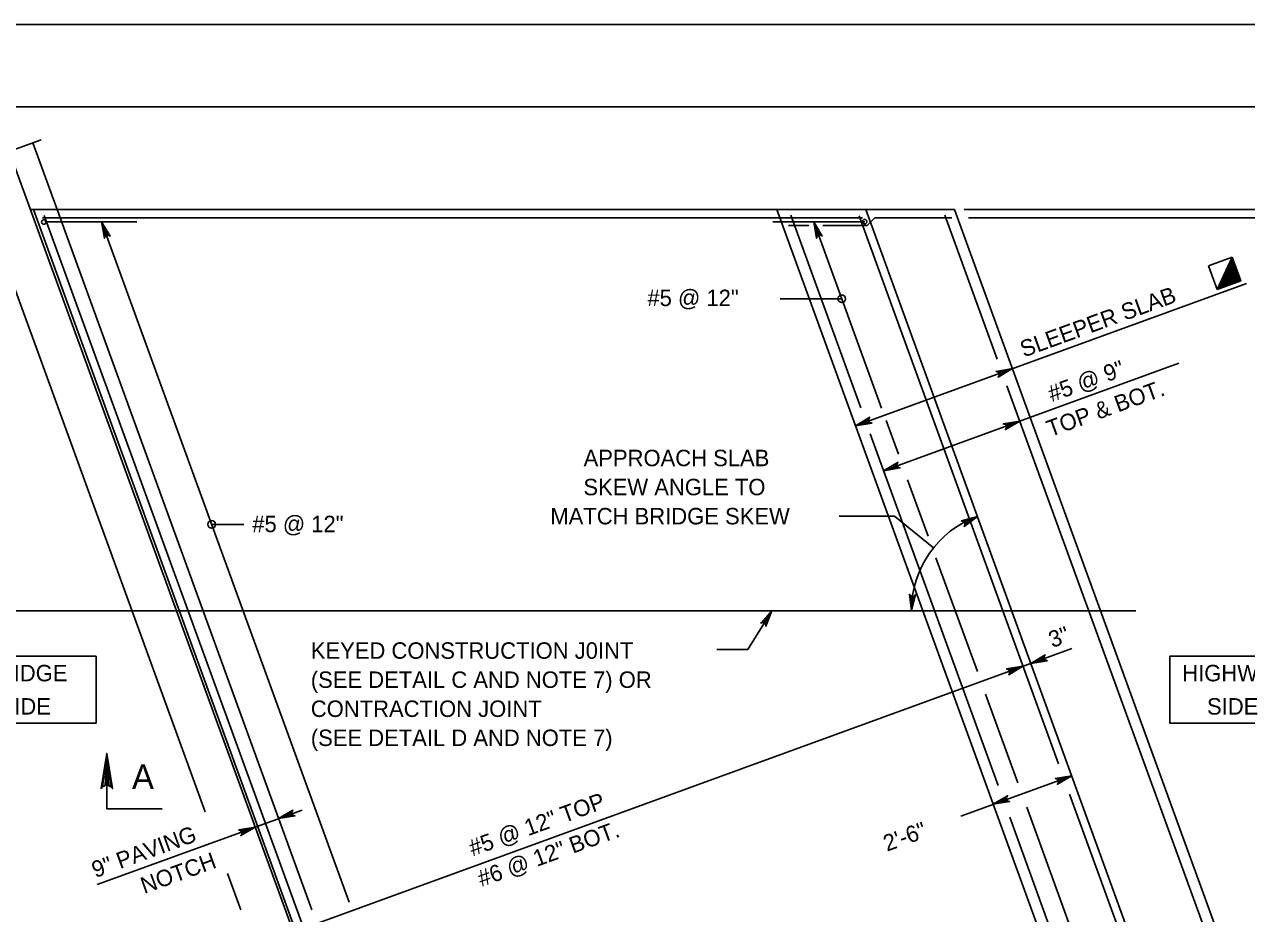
# Model space of a CAD drawing. Extents: x 638079 to 640019, y 297691 to 298879.
# Drawn here: x 638387.1 to 638610.1, y 298717.1 to 298879.2 of the extents above; entities that cross this region are included whole.
import ezdxf

# ---------------------------------------------------------------- set-up
doc = ezdxf.new("R2010")
doc.units = 0
doc.layers.add('1', color=7, linetype='Continuous')
doc.layers.add('PLT-BNDY', color=7, linetype='Continuous')

msp = doc.modelspace()

# ---------------------------------------------------------------- linework, layer by layer
at = {"layer": '1'}
for p, q in [((638383.51, 298855.78), (638390.17, 298858.2)), ((638393.1, 298845.46), (638388.66, 298857.65)), ((638435.54, 298715.48), (638384.36, 298856.09)), ((638420.09, 298735.64), (638377.2, 298853.48)), ((638388.23, 298845.46), (638540.63, 298845.46)), ((638442.02, 298699.15), (638388.77, 298845.46)), ((638439.58, 298717.75), (638393.1, 298845.46)), ((638577.66, 298699.15), (638524.41, 298845.46)), ((638540.63, 298845.46), (638556.85, 298845.46)), ((638593.88, 298699.15), (638540.63, 298845.46)), ((638610.1, 298699.15), (638556.85, 298845.46)), ((638558.6, 298845.46), (638679.01, 298845.46)), ((638390.44, 298843.93), (638540.07, 298843.93)), ((638443.26, 298700.2), (638390.77, 298844.41)), ((638390.86, 298843.21), (638407.62, 298843.21)), ((638446.37, 298719.18), (638401.23, 298843.21)), ((638540.47, 298843.24), (638523.7, 298843.24)), ((638539.74, 298809.29), (638526.95, 298844.42)), ((638543.53, 298809.23), (638531.15, 298843.24)), ((638575.8, 298744.38), (638539.42, 298844.32)), ((638540.91, 298842.55), (638542.29, 298843.93)), ((638542.29, 298843.93), (638556.32, 298843.93)), ((638564.61, 298818.19), (638555.06, 298844.44)), ((638559.41, 298843.93), (638663.72, 298843.93)), ((638526.55, 298842.55), (638530.27, 298842.55)), ((638532.83, 298842.55), (638540.91, 298842.55)), ((638603.18, 298835.19), (638607.48, 298836.76)), ((638607.48, 298836.76), (638604.74, 298830.9)), ((638607.5, 298836.69), (638604.8, 298830.92)), ((638607.52, 298836.63), (638604.87, 298830.94)), ((638607.54, 298836.57), (638604.93, 298830.96)), ((638607.56, 298836.51), (638604.99, 298830.98)), ((638609.04, 298832.46), (638607.48, 298836.76)), ((638604.74, 298830.9), (638603.18, 298835.19)), ((638607.59, 298836.45), (638605.05, 298831.01)), ((638607.61, 298836.39), (638605.11, 298831.03)), ((638607.63, 298836.33), (638605.17, 298831.05)), ((638607.65, 298836.27), (638605.23, 298831.07)), ((638607.68, 298836.21), (638605.29, 298831.09)), ((638607.7, 298836.15), (638605.35, 298831.12)), ((638607.72, 298836.09), (638605.41, 298831.14)), ((638607.74, 298836.03), (638605.47, 298831.16)), ((638607.76, 298835.97), (638605.53, 298831.18)), ((638607.79, 298835.9), (638605.59, 298831.21)), ((638607.81, 298835.84), (638605.65, 298831.23)), ((638607.83, 298835.78), (638605.72, 298831.25)), ((638607.85, 298835.72), (638605.78, 298831.27)), ((638607.87, 298835.66), (638605.84, 298831.29)), ((638607.9, 298835.6), (638605.9, 298831.32)), ((638607.92, 298835.54), (638605.96, 298831.34)), ((638607.94, 298835.48), (638606.02, 298831.36)), ((638607.96, 298835.42), (638606.08, 298831.38)), ((638607.98, 298835.36), (638606.14, 298831.4)), ((638608.01, 298835.3), (638606.2, 298831.43)), ((638608.03, 298835.24), (638606.26, 298831.45)), ((638608.05, 298835.18), (638606.32, 298831.47)), ((638608.07, 298835.12), (638606.38, 298831.49)), ((638608.1, 298835.05), (638606.44, 298831.51)), ((638608.12, 298834.99), (638606.51, 298831.54)), ((638608.14, 298834.93), (638606.57, 298831.56)), ((638608.16, 298834.87), (638606.63, 298831.58)), ((638608.18, 298834.81), (638606.69, 298831.6)), ((638608.21, 298834.75), (638606.75, 298831.63)), ((638608.23, 298834.69), (638606.81, 298831.65)), ((638608.25, 298834.63), (638606.87, 298831.67)), ((638608.27, 298834.57), (638606.93, 298831.69)), ((638608.29, 298834.51), (638606.99, 298831.71)), ((638608.32, 298834.45), (638607.05, 298831.74)), ((638608.34, 298834.39), (638607.11, 298831.76)), ((638608.36, 298834.33), (638607.17, 298831.78)), ((638608.38, 298834.26), (638607.23, 298831.8)), ((638604.74, 298830.9), (638609.04, 298832.46)), ((638608.4, 298834.2), (638607.3, 298831.82)), ((638608.43, 298834.14), (638607.36, 298831.85)), ((638608.45, 298834.08), (638607.42, 298831.87)), ((638608.47, 298834.02), (638607.48, 298831.89)), ((638608.49, 298833.96), (638607.54, 298831.91)), ((638608.52, 298833.9), (638607.6, 298831.93)), ((638608.54, 298833.84), (638607.66, 298831.96)), ((638608.56, 298833.78), (638607.72, 298831.98)), ((638608.58, 298833.72), (638607.78, 298832)), ((638608.6, 298833.66), (638607.84, 298832.02)), ((638608.63, 298833.6), (638607.9, 298832.05)), ((638608.65, 298833.54), (638607.96, 298832.07)), ((638608.67, 298833.47), (638608.02, 298832.09)), ((638608.69, 298833.41), (638608.09, 298832.11)), ((638608.71, 298833.35), (638608.15, 298832.13)), ((638608.74, 298833.29), (638608.21, 298832.16)), ((638608.76, 298833.23), (638608.27, 298832.18)), ((638608.78, 298833.17), (638608.33, 298832.2)), ((638608.8, 298833.11), (638608.39, 298832.22)), ((638608.83, 298833.05), (638608.45, 298832.24)), ((638608.85, 298832.99), (638608.51, 298832.27)), ((638608.87, 298832.93), (638608.57, 298832.29)), ((638608.89, 298832.87), (638608.63, 298832.31)), ((638608.91, 298832.81), (638608.69, 298832.33)), ((638608.94, 298832.75), (638608.75, 298832.36)), ((638608.96, 298832.68), (638608.81, 298832.38)), ((638608.98, 298832.62), (638608.88, 298832.4)), ((638609, 298832.56), (638608.94, 298832.42)), ((638609.02, 298832.5), (638609, 298832.44)), ((638538.76, 298806.03), (638610.07, 298831.98)), ((638525.05, 298829.19), (638536.27, 298829.19)), ((638597.78, 298817.45), (638543.9, 298797.84)), ((638607.57, 298700.17), (638566.39, 298813.29)), ((638546.59, 298800.83), (638544.34, 298807.01)), ((638564.81, 298740.4), (638541.45, 298804.59)), ((638552.03, 298785.88), (638548.27, 298796.2)), ((638421.3, 298788.05), (638427.2, 298788.05)), ((638535.81, 298789.57), (638545.85, 298789.57)), ((638553.02, 298783.79), (638545.85, 298789.57)), ((638561, 298761.23), (638553.45, 298781.98)), ((638380.22, 298772.31), (638589.89, 298772.31)), ((638519.13, 298765.23), (638523.51, 298772.31)), ((638578.26, 298765.43), (638427.32, 298710.49)), ((638513.45, 298765.23), (638519.13, 298765.23)), ((638568.39, 298740.92), (638562.51, 298757.09)), ((638557.98, 298734.85), (638578.21, 298742.22)), ((638592.03, 298699.79), (638577.8, 298738.87)), ((638582.78, 298701.4), (638570.02, 298736.46)), ((638400.44, 298722.35), (638437.84, 298735.96)), ((638579.45, 298700.17), (638566.91, 298734.64)), ((638426.6, 298717.77), (638424.19, 298724.39))]:
    msp.add_line(p, q, dxfattribs=at)
for points in [[(639099.03, 298300.23), (639099.03, 298864.23), (638313.03, 298864.23), (638313.03, 298300.23), (639099.03, 298300.23), (639099.03, 298326.59), (638899.03, 298326.59), (638899.03, 298391.26), (639099.03, 298391.26), (639099.03, 298420.23), (638899.03, 298420.23), (638899.03, 298300.23), (638977.83, 298300.23), (638977.83, 298326.59), (638977.83, 298300.23), (639054.83, 298300.23), (639054.83, 298326.59), (639054.83, 298314.27), (639099.03, 298314.27)], [(638401.23, 298843.21), (638402.77, 298840.6), (638402.66, 298840.68), (638402.54, 298840.76), (638402.43, 298840.78), (638402.32, 298840.8), (638402.22, 298840.79), (638402.12, 298840.77), (638402.03, 298840.72), (638401.94, 298840.67), (638401.87, 298840.58), (638401.79, 298840.49), (638401.76, 298840.35), (638401.72, 298840.22), (638401.23, 298843.21), (638401.76, 298840.35), (638401.79, 298840.49), (638401.23, 298843.21), (638401.87, 298840.58), (638401.94, 298840.67), (638401.23, 298843.21), (638402.03, 298840.72), (638402.12, 298840.77), (638401.23, 298843.21), (638402.22, 298840.79), (638402.32, 298840.8), (638401.23, 298843.21), (638402.43, 298840.78), (638402.54, 298840.76), (638401.23, 298843.21), (638402.66, 298840.68)], [(638531.15, 298843.24), (638532.7, 298840.63), (638532.58, 298840.71), (638532.47, 298840.79), (638532.36, 298840.81), (638532.24, 298840.83), (638532.14, 298840.81), (638532.04, 298840.8), (638531.95, 298840.75), (638531.87, 298840.69), (638531.79, 298840.6), (638531.72, 298840.52), (638531.68, 298840.38), (638531.65, 298840.24), (638531.15, 298843.24), (638531.68, 298840.38), (638531.72, 298840.52), (638531.15, 298843.24), (638531.79, 298840.6), (638531.87, 298840.69), (638531.15, 298843.24), (638531.95, 298840.75), (638532.04, 298840.8), (638531.15, 298843.24), (638532.14, 298840.81), (638532.24, 298840.83), (638531.15, 298843.24), (638532.36, 298840.81), (638532.47, 298840.79), (638531.15, 298843.24), (638532.58, 298840.71)], [(638567.4, 298816.46), (638564.79, 298814.91), (638564.87, 298815.02), (638564.95, 298815.14), (638564.98, 298815.25), (638565, 298815.37), (638564.98, 298815.47), (638564.96, 298815.57), (638564.91, 298815.65), (638564.86, 298815.74), (638564.77, 298815.82), (638564.68, 298815.89), (638564.54, 298815.92), (638564.41, 298815.96), (638567.4, 298816.46), (638564.54, 298815.92), (638564.68, 298815.89), (638567.4, 298816.46), (638564.77, 298815.82), (638564.86, 298815.74), (638567.4, 298816.46), (638564.91, 298815.65), (638564.96, 298815.57), (638567.4, 298816.46), (638564.98, 298815.47), (638565, 298815.37), (638567.4, 298816.46), (638564.98, 298815.25), (638564.95, 298815.14), (638567.4, 298816.46), (638564.87, 298815.02)], [(638538.76, 298806.03), (638541.37, 298807.58), (638541.29, 298807.46), (638541.21, 298807.35), (638541.19, 298807.23), (638541.17, 298807.12), (638541.19, 298807.02), (638541.21, 298806.92), (638541.26, 298806.83), (638541.31, 298806.74), (638541.4, 298806.67), (638541.49, 298806.6), (638541.62, 298806.56), (638541.76, 298806.52), (638538.76, 298806.03), (638541.62, 298806.56), (638541.49, 298806.6), (638538.76, 298806.03), (638541.4, 298806.67), (638541.31, 298806.74), (638538.76, 298806.03), (638541.26, 298806.83), (638541.21, 298806.92), (638538.76, 298806.03), (638541.19, 298807.02), (638541.17, 298807.12), (638538.76, 298806.03), (638541.19, 298807.23), (638541.21, 298807.35), (638538.76, 298806.03), (638541.29, 298807.46)], [(638568.73, 298806.88), (638566.12, 298805.33), (638566.2, 298805.45), (638566.28, 298805.56), (638566.3, 298805.67), (638566.32, 298805.79), (638566.3, 298805.89), (638566.28, 298805.99), (638566.23, 298806.08), (638566.18, 298806.16), (638566.09, 298806.24), (638566, 298806.31), (638565.87, 298806.35), (638565.73, 298806.38), (638568.73, 298806.88), (638565.87, 298806.35), (638566, 298806.31), (638568.73, 298806.88), (638566.09, 298806.24), (638566.18, 298806.16), (638568.73, 298806.88), (638566.23, 298806.08), (638566.28, 298805.99), (638568.73, 298806.88), (638566.3, 298805.89), (638566.32, 298805.79), (638568.73, 298806.88), (638566.3, 298805.67), (638566.28, 298805.56), (638568.73, 298806.88), (638566.2, 298805.45)], [(638543.9, 298797.84), (638546.52, 298799.39), (638546.44, 298799.27), (638546.35, 298799.16), (638546.33, 298799.05), (638546.31, 298798.93), (638546.33, 298798.83), (638546.35, 298798.73), (638546.4, 298798.64), (638546.45, 298798.56), (638546.54, 298798.48), (638546.63, 298798.41), (638546.76, 298798.37), (638546.9, 298798.34), (638543.9, 298797.84), (638546.76, 298798.37), (638546.63, 298798.41), (638543.9, 298797.84), (638546.54, 298798.48), (638546.45, 298798.56), (638543.9, 298797.84), (638546.4, 298798.64), (638546.35, 298798.73), (638543.9, 298797.84), (638546.33, 298798.83), (638546.31, 298798.93), (638543.9, 298797.84), (638546.33, 298799.05), (638546.35, 298799.16), (638543.9, 298797.84), (638546.44, 298799.27)], [(638561, 298789.49), (638558.57, 298787.67), (638558.64, 298787.79), (638558.71, 298787.92), (638558.72, 298788.03), (638558.72, 298788.15), (638558.7, 298788.24), (638558.67, 298788.34), (638558.61, 298788.42), (638558.55, 298788.51), (638558.45, 298788.57), (638558.35, 298788.63), (638558.22, 298788.65), (638558.08, 298788.67), (638561, 298789.49), (638558.22, 298788.65), (638558.35, 298788.63), (638561, 298789.49), (638558.45, 298788.57), (638558.55, 298788.51), (638561, 298789.49), (638558.61, 298788.42), (638558.67, 298788.34), (638561, 298789.49), (638558.7, 298788.24), (638558.72, 298788.15), (638561, 298789.49), (638558.72, 298788.03), (638558.71, 298787.92), (638561, 298789.49), (638558.64, 298787.79)], [(638548.97, 298772.31), (638548.62, 298775.32), (638548.7, 298775.2), (638548.77, 298775.08), (638548.86, 298775.01), (638548.96, 298774.95), (638549.06, 298774.92), (638549.16, 298774.9), (638549.26, 298774.91), (638549.36, 298774.92), (638549.46, 298774.97), (638549.57, 298775.02), (638549.65, 298775.13), (638549.74, 298775.24), (638548.97, 298772.31), (638549.65, 298775.13), (638549.57, 298775.02), (638548.97, 298772.31), (638549.46, 298774.97), (638549.36, 298774.92), (638548.97, 298772.31), (638549.26, 298774.91), (638549.16, 298774.9), (638548.97, 298772.31), (638549.06, 298774.92), (638548.96, 298774.95), (638548.97, 298772.31), (638548.86, 298775.01), (638548.77, 298775.08), (638548.97, 298772.31), (638548.7, 298775.2)], [(638523.51, 298772.31), (638522.42, 298769.47), (638522.41, 298769.61), (638522.4, 298769.75), (638522.35, 298769.86), (638522.29, 298769.96), (638522.22, 298770.03), (638522.14, 298770.09), (638522.05, 298770.13), (638521.95, 298770.17), (638521.84, 298770.17), (638521.72, 298770.17), (638521.59, 298770.12), (638521.47, 298770.06), (638523.51, 298772.31), (638521.59, 298770.12), (638521.72, 298770.17), (638523.51, 298772.31), (638521.84, 298770.17), (638521.95, 298770.17), (638523.51, 298772.31), (638522.05, 298770.13), (638522.14, 298770.09), (638523.51, 298772.31), (638522.22, 298770.03), (638522.29, 298769.96), (638523.51, 298772.31), (638522.35, 298769.86), (638522.4, 298769.75), (638523.51, 298772.31), (638522.41, 298769.61)], [(638570.75, 298762.7), (638573.36, 298764.24), (638573.28, 298764.13), (638573.2, 298764.02), (638573.18, 298763.9), (638573.16, 298763.79), (638573.18, 298763.69), (638573.19, 298763.59), (638573.24, 298763.5), (638573.3, 298763.41), (638573.39, 298763.34), (638573.47, 298763.26), (638573.61, 298763.23), (638573.75, 298763.19), (638570.75, 298762.7), (638573.61, 298763.23), (638573.47, 298763.26), (638570.75, 298762.7), (638573.39, 298763.34), (638573.3, 298763.41), (638570.75, 298762.7), (638573.24, 298763.5), (638573.19, 298763.59), (638570.75, 298762.7), (638573.18, 298763.69), (638573.16, 298763.79), (638570.75, 298762.7), (638573.18, 298763.9), (638573.2, 298764.02), (638570.75, 298762.7), (638573.28, 298764.13)], [(638569.32, 298762.18), (638566.71, 298760.63), (638566.79, 298760.75), (638566.87, 298760.86), (638566.89, 298760.97), (638566.91, 298761.09), (638566.89, 298761.19), (638566.88, 298761.29), (638566.83, 298761.38), (638566.78, 298761.46), (638566.69, 298761.54), (638566.6, 298761.61), (638566.46, 298761.65), (638566.33, 298761.68), (638569.32, 298762.18), (638566.46, 298761.65), (638566.6, 298761.61), (638569.32, 298762.18), (638566.69, 298761.54), (638566.78, 298761.46), (638569.32, 298762.18), (638566.83, 298761.38), (638566.88, 298761.29), (638569.32, 298762.18), (638566.89, 298761.19), (638566.91, 298761.09), (638569.32, 298762.18), (638566.89, 298760.97), (638566.87, 298760.86), (638569.32, 298762.18), (638566.79, 298760.75)], [(638401.41, 298740.17), (638401.85, 298740.4), (638402.17, 298746.28), (638401.41, 298740.17), (638401.14, 298739.86), (638402.17, 298746.28), (638402.46, 298740.4), (638402.9, 298740.19), (638402.17, 298746.28), (638403.19, 298739.86), (638402.9, 298740.19)], [(638412.25, 298736.2), (638402.17, 298736.2), (638402.17, 298746.28)], [(638578.21, 298742.22), (638575.6, 298740.67), (638575.68, 298740.78), (638575.76, 298740.9), (638575.78, 298741.01), (638575.8, 298741.13), (638575.78, 298741.23), (638575.76, 298741.33), (638575.71, 298741.41), (638575.66, 298741.5), (638575.57, 298741.58), (638575.48, 298741.65), (638575.35, 298741.69), (638575.21, 298741.72), (638578.21, 298742.22), (638575.35, 298741.69), (638575.48, 298741.65), (638578.21, 298742.22), (638575.57, 298741.58), (638575.66, 298741.5), (638578.21, 298742.22), (638575.71, 298741.41), (638575.76, 298741.33), (638578.21, 298742.22), (638575.78, 298741.23), (638575.8, 298741.13), (638578.21, 298742.22), (638575.78, 298741.01), (638575.76, 298740.9), (638578.21, 298742.22), (638575.68, 298740.78)], [(638563.89, 298737), (638566.5, 298738.55), (638566.42, 298738.43), (638566.34, 298738.32), (638566.31, 298738.21), (638566.29, 298738.09), (638566.31, 298737.99), (638566.33, 298737.89), (638566.38, 298737.8), (638566.43, 298737.72), (638566.52, 298737.64), (638566.61, 298737.57), (638566.74, 298737.53), (638566.88, 298737.5), (638563.89, 298737), (638566.74, 298737.53), (638566.61, 298737.57), (638563.89, 298737), (638566.52, 298737.64), (638566.43, 298737.72), (638563.89, 298737), (638566.38, 298737.8), (638566.33, 298737.89), (638563.89, 298737), (638566.31, 298737.99), (638566.29, 298738.09), (638563.89, 298737), (638566.31, 298738.21), (638566.34, 298738.32), (638563.89, 298737), (638566.42, 298738.43)], [(638433.52, 298734.39), (638436.13, 298735.93), (638436.05, 298735.82), (638435.97, 298735.7), (638435.95, 298735.59), (638435.93, 298735.48), (638435.95, 298735.38), (638435.96, 298735.28), (638436.02, 298735.19), (638436.07, 298735.1), (638436.16, 298735.03), (638436.25, 298734.95), (638436.38, 298734.92), (638436.52, 298734.88), (638433.52, 298734.39), (638436.38, 298734.92), (638436.25, 298734.95), (638433.52, 298734.39), (638436.16, 298735.03), (638436.07, 298735.1), (638433.52, 298734.39), (638436.02, 298735.19), (638435.96, 298735.28), (638433.52, 298734.39), (638435.95, 298735.38), (638435.93, 298735.48), (638433.52, 298734.39), (638435.95, 298735.59), (638435.97, 298735.7), (638433.52, 298734.39), (638436.05, 298735.82)], [(638429.23, 298732.82), (638426.61, 298731.28), (638426.69, 298731.39), (638426.78, 298731.51), (638426.8, 298731.62), (638426.82, 298731.73), (638426.8, 298731.83), (638426.78, 298731.93), (638426.73, 298732.02), (638426.68, 298732.11), (638426.59, 298732.18), (638426.5, 298732.26), (638426.37, 298732.29), (638426.23, 298732.33), (638429.23, 298732.82), (638426.37, 298732.29), (638426.5, 298732.26), (638429.23, 298732.82), (638426.59, 298732.18), (638426.68, 298732.11), (638429.23, 298732.82), (638426.73, 298732.02), (638426.78, 298731.93), (638429.23, 298732.82), (638426.8, 298731.83), (638426.82, 298731.73), (638429.23, 298732.82), (638426.8, 298731.62), (638426.78, 298731.51), (638429.23, 298732.82), (638426.69, 298731.39)]]:
    msp.add_lwpolyline(points, dxfattribs=at)
for points in [[(638375.82, 298751.82), (638400.21, 298751.82), (638400.21, 298764.01), (638375.82, 298764.01)], [(638596.11, 298751.82), (638620.5, 298751.82), (638620.5, 298764.01), (638596.11, 298764.01)]]:
    msp.add_lwpolyline(points, close=True, dxfattribs=at)
for centre, radius in [((638390.67, 298843.19), 0.414), ((638540.44, 298843.27), 0.414), ((638536.27, 298829.19), 0.694), ((638421.3, 298788.05), 0.694)]:
    msp.add_circle(centre, radius, dxfattribs=at)
msp.add_arc((638567.25, 298772.31), 18.29, 110, 180, dxfattribs=at)
at = {"layer": 'PLT-BNDY'}
msp.add_lwpolyline([(638274.03, 298879.23), (639115.03, 298879.23), (639115.03, 298285.23), (638274.03, 298285.23)], close=True, dxfattribs=at)

# ---------------------------------------------------------------- texts
at = {"layer": '1'}
for s, height, p in [('#5 @ 12"', 3, (638500.8, 298827.86)), ('APPROACH SLAB', 3, (638489.16, 298798.66)), ('SKEW ANGLE TO', 3, (638489.12, 298793.36)), ('#5 @ 12"', 3, (638428.71, 298786.63)), ('MATCH BRIDGE SKEW', 3, (638483.09, 298788.05)), ('KEYED CONSTRUCTION J0INT', 3, (638439.39, 298763.54)), ('BRIDGE', 3, (638379.61, 298759.43)), ('(SEE DETAIL C AND NOTE 7) OR', 3, (638439.39, 298758.23)), ('HIGHWAY', 3, (638598.38, 298759.43)), ('SIDE', 3, (638382.61, 298753.36)), ('SIDE', 3, (638602.9, 298753.36)), ('CONTRACTION JOINT', 3, (638439.39, 298752.93)), ('(SEE DETAIL D AND NOTE 7)', 3, (638439.39, 298747.63)), ('A', 4.5, (638406.76, 298739.78))]:
    msp.add_text(s, height=height, dxfattribs=at).set_placement(p)
for s, p in [('SLEEPER SLAB', (638569.46, 298818.47)), ('#5 @ 9"', (638574.57, 298810.32)), ('TOP & BOT.', (638574.3, 298803.96)), ('3"', (638574.66, 298765.49)), ('#5 @ 12" TOP', (638468.9, 298727.49)), ('9" PAVING', (638400.09, 298723.54)), ('#6 @ 12" BOT.', (638470.51, 298721.9)), ('2\'-6"', (638544.5, 298728.34)), ('NOTCH', (638409, 298720.64))]:
    msp.add_text(s, height=3, rotation=20, dxfattribs=at).set_placement(p)

doc.saveas('drawing.dxf')
